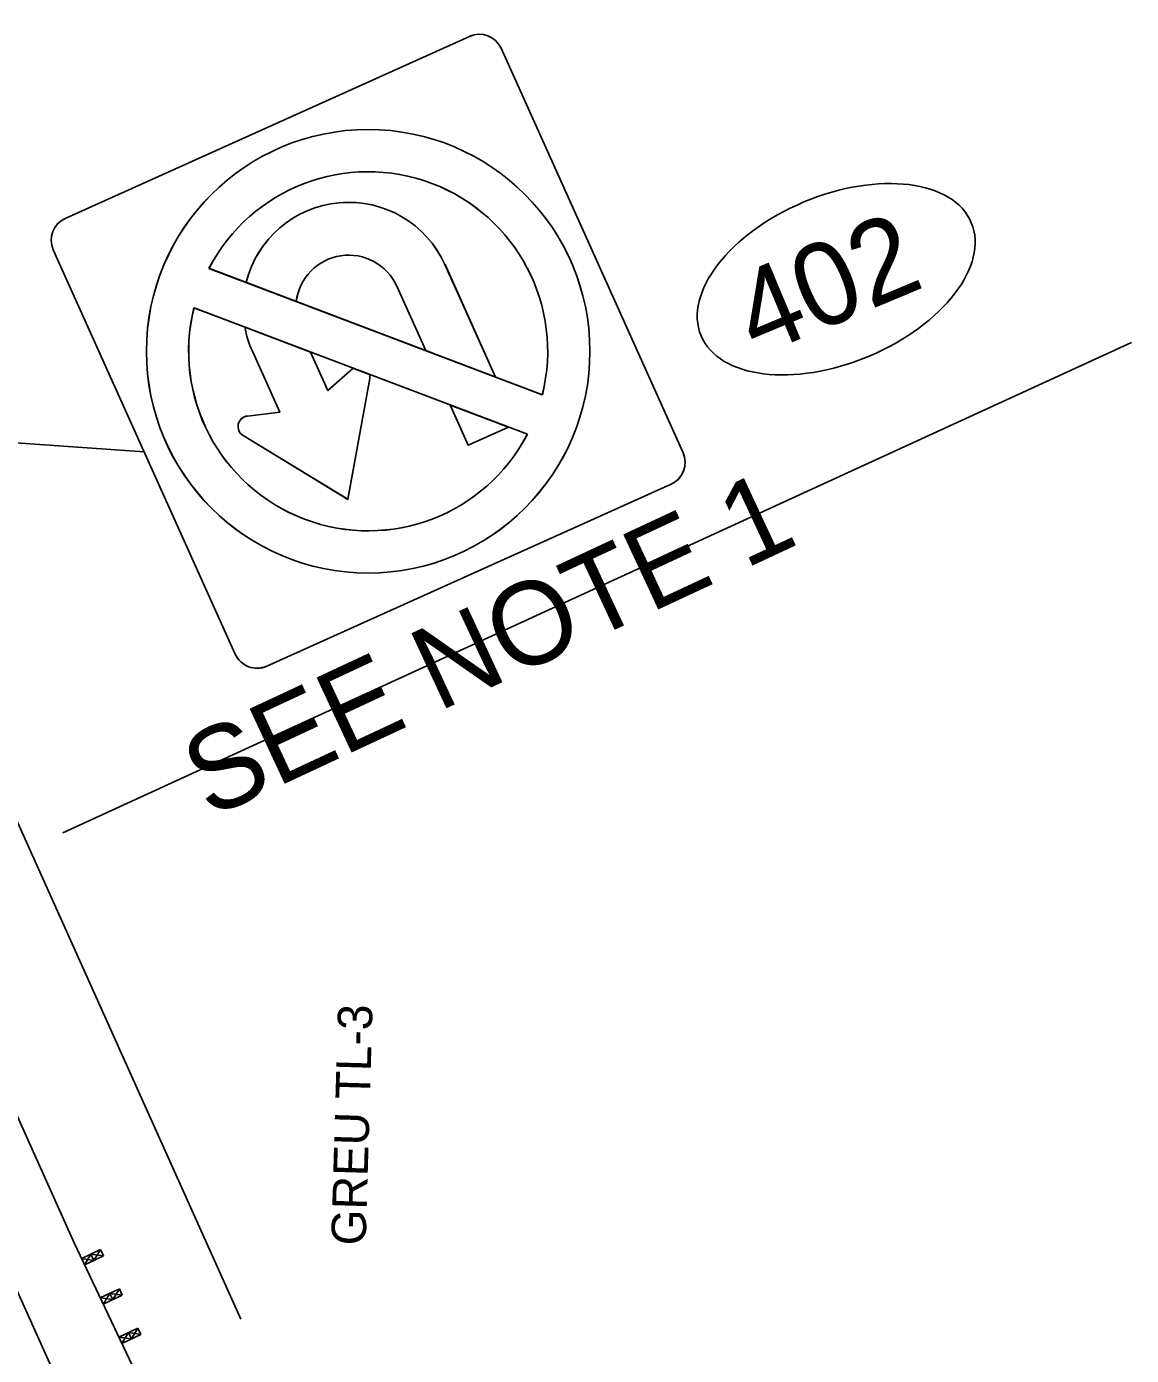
# Model space of a CAD drawing. Extents: x 2096670 to 2098561, y 684033 to 689893.
# Drawn here: x 2097858.5 to 2098018.6, y 685641.1 to 685833.7 of the extents above; entities that cross this region are included whole.
import ezdxf

# ---------------------------------------------------------------- set-up
doc = ezdxf.new("R2010")
doc.units = 0
for name, color, linetype in [('Exist Sign E No U Turn CELL', 7, 'Continuous'), ('Prop DSN Text', 7, 'Continuous'), ('Prop Guardrail', 7, 'Continuous'), ('Prop Guardrail Anchor Unit CELL', 7, 'Continuous'), ('Prop Sign E One Way_Right CELL', 7, 'Continuous'), ('Prop Sign E Signal Light Ahead CELL', 7, 'Continuous'), ('Scratch_Level_3', 7, 'Continuous'), ('Scratch_Level_4', 7, 'Continuous')]:
    doc.layers.add(name, color=color, linetype=linetype)

# ---------------------------------------------------------------- blocks, each defined once
blk = doc.blocks.new('Exist No U Turn')
at = {"layer": 'Exist Sign E No U Turn CELL'}
for p, q in [((56.27, 62.3), (-56.61, 62.3)), ((-62.66, 56.26), (-62.66, -56.62)), ((62.31, -56.62), (62.31, 56.26)), ((-28.46, 35.7), (35.71, -28.46)), ((-28.46, 35.7), (-28.46, 35.7)), ((-36.06, 28.1), (28.11, -36.06)), ((-36.06, 28.1), (-36.06, 28.1)), ((-21.29, 28.54), (-11.65, 18.9)), ((-21.29, 28.54), (-11.65, 18.9)), ((-21.29, 28.54), (-11.65, 18.9)), ((-11.65, 18.9), (-11.65, 18.9)), ((-11.65, 18.9), (-11.65, 18.9)), ((-11.65, 18.9), (-11.65, 18.9)), ((-2.25, -5.71), (-5.43, -2.52)), ((-2.67, -6.68), (-2.67, -6.68)), ((-2.67, -6.68), (-2.67, -6.68)), ((-56.61, -62.67), (56.27, -62.67))]:
    blk.add_line(p, q, dxfattribs=at)
for points in [[(-2.25, -5.71), (-5.45, -2.51), (-13.61, -5.1), (-13.61, 5.66), (-26.27, 18.32)], [(-5.72, -2.6), (-13.61, -5.1), (-13.61, 5.66), (-26.27, 18.32)], [(-2.25, -5.71), (-5.45, -2.51), (-13.61, -5.1), (-13.61, 5.66), (-26.27, 18.32)], [(-27.05, 11.91), (-27.05, -5.1), (-34.96, -2.59)], [(-27.05, 11.91), (-27.05, -5.1), (-34.96, -2.59)], [(-27.05, 11.91), (-27.05, -5.1), (-34.96, -2.59)], [(13.27, 11.91), (13.27, -6.02), (26.7, -19.46), (26.7, 11.91)], [(13.27, 11.91), (13.27, -6.02), (26.7, -19.46), (26.7, 11.91)], [(13.27, 11.91), (13.27, -6.02), (26.7, -19.46), (26.7, 11.91)], [(-38, -6.67), (-20.33, -32.43), (-2.67, -6.68)], [(-38, -6.67), (-20.33, -32.43), (-2.67, -6.68)], [(-38, -6.67), (-20.33, -32.43), (-2.67, -6.68)]]:
    blk.add_lwpolyline(points, dxfattribs=at)
blk.add_lwpolyline([(13.27, -21.22), (13.27, -32.43), (24.48, -32.43)], close=True, dxfattribs=at)
blk.add_lwpolyline([(13.27, -21.22), (13.27, -32.43), (24.48, -32.43)], close=True, dxfattribs=at)
blk.add_lwpolyline([(13.27, -21.22), (13.27, -32.43), (24.48, -32.43)], close=True, dxfattribs=at)
blk.add_circle((-0.17, -0.18), 56.44, dxfattribs=at)
for centre, radius, start, end in [((-56.61, 56.26), 6.05, 90, 180), ((56.27, 56.26), 6.05, 0, 90), ((-0.17, -0.18), 45.69, 321.7553, 128.2447), ((-0.17, 11.91), 26.88, 359.9928, 141.788), ((-0.17, 11.91), 26.88, 359.9928, 141.788), ((-0.17, 11.91), 26.88, 359.9928, 141.788), ((-0.17, -0.18), 45.69, 141.7553, 308.2447), ((-0.17, 11.91), 13.44, 0, 148.6739), ((-0.17, 11.91), 13.44, 0, 148.6739), ((-0.17, 11.91), 13.44, 0, 148.6739), ((-0.17, 11.91), 26.87, 166.2094, 180), ((-0.17, 11.91), 26.87, 166.2094, 180), ((-0.17, 11.91), 26.87, 166.2094, 180), ((-35.78, -5.15), 2.69, 72.3746, 214.4704), ((-35.78, -5.15), 2.69, 72.3746, 214.4704), ((-35.78, -5.15), 2.69, 72.3746, 214.4704), ((-4.9, -5.14), 2.67, 101.5336, 108.0305), ((-4.9, -5.14), 2.67, 101.5336, 107.1991), ((-4.9, -5.14), 2.67, 101.5336, 107.1991), ((-4.88, -5.15), 2.69, 325.4527, 348.1626), ((-4.88, -5.15), 2.69, 325.4527, 348.1626), ((-4.88, -5.15), 2.69, 325.4527, 348.1626), ((-56.61, -56.62), 6.05, 180, 270), ((56.27, -56.62), 6.05, 270, 0)]:
    blk.add_arc(centre, radius, start, end, dxfattribs=at)

msp = doc.modelspace()

# ---------------------------------------------------------------- linework, layer by layer
at = {"layer": 'Exist Sign E No U Turn CELL'}
for p, q in [((2097922.67, 685832.24), (2097864.06, 685805.86)), ((2097953.6, 685771.91), (2097927.22, 685830.52)), ((2097862.34, 685801.31), (2097888.71, 685742.71)), ((2097884.9, 685798.63), (2097933.21, 685780.31)), ((2097884.9, 685798.63), (2097884.9, 685798.63)), ((2097890.29, 685796.59), (2097897.55, 685793.83)), ((2097890.29, 685796.59), (2097897.55, 685793.83)), ((2097890.29, 685796.59), (2097897.55, 685793.83)), ((2097882.73, 685792.91), (2097931.04, 685774.59)), ((2097882.73, 685792.91), (2097882.73, 685792.91)), ((2097897.55, 685793.83), (2097897.55, 685793.83)), ((2097897.55, 685793.83), (2097897.55, 685793.83)), ((2097897.55, 685793.83), (2097897.55, 685793.83)), ((2097908.18, 685783.26), (2097905.78, 685784.17)), ((2097908.19, 685782.65), (2097908.19, 685782.65)), ((2097908.19, 685782.65), (2097908.19, 685782.65)), ((2097893.26, 685740.98), (2097951.87, 685767.36))]:
    msp.add_line(p, q, dxfattribs=at)
for points in [[(2097912.12, 685796.03), (2097916.31, 685786.72), (2097926.42, 685782.88), (2097919.1, 685799.17)], [(2097912.12, 685796.03), (2097916.31, 685786.72), (2097926.42, 685782.88), (2097919.1, 685799.17)], [(2097912.12, 685796.03), (2097916.31, 685786.72), (2097926.42, 685782.88), (2097919.1, 685799.17)], [(2097908.18, 685783.26), (2097905.77, 685784.17), (2097902.14, 685780.91), (2097899.63, 685786.5), (2097890.09, 685790.12)], [(2097905.65, 685784.06), (2097902.14, 685780.91), (2097899.63, 685786.5), (2097890.09, 685790.12)], [(2097908.18, 685783.26), (2097905.77, 685784.17), (2097902.14, 685780.91), (2097899.63, 685786.5), (2097890.09, 685790.12)], [(2097891.19, 685786.61), (2097895.16, 685777.77), (2097890.47, 685777.23)], [(2097891.19, 685786.61), (2097895.16, 685777.77), (2097890.47, 685777.23)], [(2097891.19, 685786.61), (2097895.16, 685777.77), (2097890.47, 685777.23)], [(2097889.85, 685774.4), (2097905.04, 685765.16), (2097908.19, 685782.65)], [(2097889.85, 685774.4), (2097905.04, 685765.16), (2097908.19, 685782.65)], [(2097889.85, 685774.4), (2097905.04, 685765.16), (2097908.19, 685782.65)]]:
    msp.add_lwpolyline(points, dxfattribs=at)
msp.add_lwpolyline([(2097919.86, 685778.83), (2097922.48, 685773.01), (2097928.3, 685775.63)], close=True, dxfattribs=at)
msp.add_lwpolyline([(2097919.86, 685778.83), (2097922.48, 685773.01), (2097928.3, 685775.63)], close=True, dxfattribs=at)
msp.add_lwpolyline([(2097919.86, 685778.83), (2097922.48, 685773.01), (2097928.3, 685775.63)], close=True, dxfattribs=at)
msp.add_circle((2097907.97, 685786.61), 32.13, dxfattribs=at)
for centre, radius, start, end in [((2097924.08, 685829.1), 3.44, 24.2309, 114.2309), ((2097907.97, 685786.61), 26.01, 345.9862, 152.4756), ((2097905.14, 685792.89), 15.3, 24.2237, 166.0189), ((2097905.14, 685792.89), 15.3, 24.2237, 166.0189), ((2097905.14, 685792.89), 15.3, 24.2237, 166.0189), ((2097865.48, 685802.73), 3.44, 114.2309, 204.2309), ((2097905.14, 685792.89), 7.65, 24.2309, 172.9048), ((2097905.14, 685792.89), 7.65, 24.2309, 172.9048), ((2097905.14, 685792.89), 7.65, 24.2309, 172.9048), ((2097907.97, 685786.61), 26.01, 165.9862, 332.4756), ((2097905.14, 685792.89), 15.3, 190.4403, 204.2309), ((2097905.14, 685792.89), 15.3, 190.4403, 204.2309), ((2097905.14, 685792.89), 15.3, 190.4403, 204.2309), ((2097906.67, 685782.93), 1.52, 125.7645, 132.2614), ((2097906.67, 685782.93), 1.52, 125.7645, 131.4301), ((2097906.67, 685782.93), 1.52, 125.7645, 131.4301), ((2097906.68, 685782.93), 1.53, 349.6837, 12.3936), ((2097906.68, 685782.93), 1.53, 349.6837, 12.3936), ((2097906.68, 685782.93), 1.53, 349.6837, 12.3936), ((2097890.64, 685775.71), 1.53, 96.6056, 238.7013), ((2097890.64, 685775.71), 1.53, 96.6056, 238.7013), ((2097890.64, 685775.71), 1.53, 96.6056, 238.7013), ((2097950.46, 685770.5), 3.44, 294.2309, 24.2309), ((2097891.85, 685744.12), 3.44, 204.2309, 294.2309)]:
    msp.add_arc(centre, radius, start, end, dxfattribs=at)
at = {"layer": 'Prop Guardrail'}
msp.add_line((2097865.36, 685657.45), (2097794.79, 685814.25), dxfattribs=at)
at = {"layer": 'Prop Guardrail Anchor Unit CELL'}
for p, q in [((2097865.36, 685657.45), (2097885.4, 685615.21)), ((2097866.45, 685655.15), (2097869.16, 685656.44)), ((2097868.23, 685654.89), (2097869.16, 685656.44)), ((2097869.16, 685656.44), (2097869.59, 685655.53)), ((2097866.45, 685655.15), (2097866.88, 685654.25)), ((2097868.23, 685654.89), (2097866.45, 685655.15)), ((2097867.8, 685655.79), (2097866.88, 685654.25)), ((2097866.88, 685654.25), (2097869.59, 685655.53)), ((2097866.88, 685654.25), (2097868.23, 685654.89)), ((2097867.8, 685655.79), (2097868.23, 685654.89)), ((2097869.59, 685655.53), (2097867.8, 685655.79)), ((2097869.15, 685649.46), (2097871.91, 685650.76)), ((2097870.96, 685649.21), (2097871.91, 685650.76)), ((2097871.91, 685650.76), (2097872.34, 685649.86)), ((2097869.15, 685649.46), (2097870.96, 685649.21)), ((2097870.53, 685650.11), (2097869.58, 685648.55)), ((2097869.58, 685648.55), (2097872.34, 685649.86)), ((2097870.53, 685650.11), (2097870.96, 685649.21)), ((2097872.34, 685649.86), (2097870.53, 685650.11)), ((2097871.85, 685643.76), (2097874.6, 685645.07)), ((2097873.23, 685644.42), (2097872.28, 685642.86)), ((2097873.23, 685644.42), (2097873.66, 685643.51)), ((2097875.03, 685644.17), (2097873.23, 685644.42)), ((2097873.66, 685643.51), (2097874.6, 685645.07)), ((2097874.6, 685645.07), (2097875.03, 685644.17)), ((2097871.85, 685643.76), (2097873.66, 685643.51)), ((2097872.28, 685642.86), (2097875.03, 685644.17))]:
    msp.add_line(p, q, dxfattribs=at)
at = {"layer": 'Prop Sign E One Way_Right CELL'}
msp.add_ellipse((2097975.79, 685797.05), major_axis=(-19.58, -8.19), ratio=0.571429, dxfattribs=at)
at = {"layer": 'Prop Sign E Signal Light Ahead CELL'}
for p, q in [((2097922.67, 685832.24), (2097864.06, 685805.86)), ((2097953.6, 685771.91), (2097927.22, 685830.52)), ((2097862.34, 685801.31), (2097888.71, 685742.71)), ((2097884.9, 685798.63), (2097933.21, 685780.31)), ((2097884.9, 685798.63), (2097884.9, 685798.63)), ((2097890.29, 685796.59), (2097897.55, 685793.83)), ((2097890.29, 685796.59), (2097897.55, 685793.83)), ((2097890.29, 685796.59), (2097897.55, 685793.83)), ((2097882.73, 685792.91), (2097931.04, 685774.59)), ((2097882.73, 685792.91), (2097882.73, 685792.91)), ((2097897.55, 685793.83), (2097897.55, 685793.83)), ((2097897.55, 685793.83), (2097897.55, 685793.83)), ((2097897.55, 685793.83), (2097897.55, 685793.83)), ((2097908.18, 685783.26), (2097905.78, 685784.17)), ((2097908.19, 685782.65), (2097908.19, 685782.65)), ((2097908.19, 685782.65), (2097908.19, 685782.65)), ((2097875.52, 685772.02), (2097773.38, 685779.3)), ((2097893.26, 685740.98), (2097951.87, 685767.36))]:
    msp.add_line(p, q, dxfattribs=at)
for points in [[(2097912.12, 685796.03), (2097916.31, 685786.72), (2097926.42, 685782.88), (2097919.1, 685799.17)], [(2097912.12, 685796.03), (2097916.31, 685786.72), (2097926.42, 685782.88), (2097919.1, 685799.17)], [(2097912.12, 685796.03), (2097916.31, 685786.72), (2097926.42, 685782.88), (2097919.1, 685799.17)], [(2097908.18, 685783.26), (2097905.77, 685784.17), (2097902.14, 685780.91), (2097899.63, 685786.5), (2097890.09, 685790.12)], [(2097905.65, 685784.06), (2097902.14, 685780.91), (2097899.63, 685786.5), (2097890.09, 685790.12)], [(2097908.18, 685783.26), (2097905.77, 685784.17), (2097902.14, 685780.91), (2097899.63, 685786.5), (2097890.09, 685790.12)], [(2097891.19, 685786.61), (2097895.16, 685777.77), (2097890.47, 685777.23)], [(2097891.19, 685786.61), (2097895.16, 685777.77), (2097890.47, 685777.23)], [(2097891.19, 685786.61), (2097895.16, 685777.77), (2097890.47, 685777.23)], [(2097889.85, 685774.4), (2097905.04, 685765.16), (2097908.19, 685782.65)], [(2097889.85, 685774.4), (2097905.04, 685765.16), (2097908.19, 685782.65)], [(2097889.85, 685774.4), (2097905.04, 685765.16), (2097908.19, 685782.65)]]:
    msp.add_lwpolyline(points, dxfattribs=at)
msp.add_lwpolyline([(2097919.86, 685778.83), (2097922.48, 685773.01), (2097928.3, 685775.63)], close=True, dxfattribs=at)
msp.add_lwpolyline([(2097919.86, 685778.83), (2097922.48, 685773.01), (2097928.3, 685775.63)], close=True, dxfattribs=at)
msp.add_lwpolyline([(2097919.86, 685778.83), (2097922.48, 685773.01), (2097928.3, 685775.63)], close=True, dxfattribs=at)
msp.add_circle((2097907.97, 685786.61), 32.13, dxfattribs=at)
for centre, radius, start, end in [((2097924.08, 685829.1), 3.44, 24.2309, 114.2309), ((2097907.97, 685786.61), 26.01, 345.9862, 152.4756), ((2097905.14, 685792.89), 15.3, 24.2237, 166.0189), ((2097905.14, 685792.89), 15.3, 24.2237, 166.0189), ((2097905.14, 685792.89), 15.3, 24.2237, 166.0189), ((2097865.48, 685802.73), 3.44, 114.2309, 204.2309), ((2097905.14, 685792.89), 7.65, 24.2309, 172.9048), ((2097905.14, 685792.89), 7.65, 24.2309, 172.9048), ((2097905.14, 685792.89), 7.65, 24.2309, 172.9048), ((2097907.97, 685786.61), 26.01, 165.9862, 332.4756), ((2097905.14, 685792.89), 15.3, 190.4403, 204.2309), ((2097905.14, 685792.89), 15.3, 190.4403, 204.2309), ((2097905.14, 685792.89), 15.3, 190.4403, 204.2309), ((2097906.67, 685782.93), 1.52, 125.7645, 132.2614), ((2097906.67, 685782.93), 1.52, 125.7645, 131.4301), ((2097906.67, 685782.93), 1.52, 125.7645, 131.4301), ((2097906.68, 685782.93), 1.53, 349.6837, 12.3936), ((2097906.68, 685782.93), 1.53, 349.6837, 12.3936), ((2097906.68, 685782.93), 1.53, 349.6837, 12.3936), ((2097890.64, 685775.71), 1.53, 96.6056, 238.7013), ((2097890.64, 685775.71), 1.53, 96.6056, 238.7013), ((2097890.64, 685775.71), 1.53, 96.6056, 238.7013), ((2097950.46, 685770.5), 3.44, 294.2309, 24.2309), ((2097891.85, 685744.12), 3.44, 204.2309, 294.2309)]:
    msp.add_arc(centre, radius, start, end, dxfattribs=at)
at = {"layer": 'Scratch_Level_3'}
msp.add_line((2097863.72, 685716.84), (2098018.57, 685787.89), dxfattribs=at)
at = {"layer": 'Scratch_Level_4'}
msp.add_line((2097889.53, 685646.39), (2097810.74, 685821.44), dxfattribs=at)
msp.add_lwpolyline([(2097918.23, 685516.37), (2097897.05, 685562.45), (2097876.09, 685608.28), (2097855.55, 685653.89), (2097835.25, 685699.31)], dxfattribs=at)

# ---------------------------------------------------------------- block references
at = {"layer": 'Prop Sign E One Way_Right CELL', "xscale": 0.5693769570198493, "yscale": 0.5693769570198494, "rotation": 24.230915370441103}
msp.add_blockref('Exist No U Turn', (2097908.01, 685786.74), dxfattribs=at)
at = {"layer": 'Prop Sign E Signal Light Ahead CELL', "xscale": 0.5693769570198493, "yscale": 0.5693769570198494, "rotation": 24.230915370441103}
msp.add_blockref('Exist No U Turn', (2097908.01, 685786.74), dxfattribs=at)

# ---------------------------------------------------------------- texts
at = {"layer": 'Prop DSN Text'}
msp.add_text('SEE NOTE 1', height=12, rotation=25.0045, dxfattribs=at).set_placement((2097884.97, 685718.86))
at = {"layer": 'Prop Guardrail Anchor Unit CELL'}
msp.add_text('GREU TL-3', height=5, rotation=88.3348, dxfattribs=at).set_placement((2097907.6, 685657))
at = {"layer": 'Prop Sign E One Way_Right CELL'}
msp.add_text('402', height=11.98, rotation=22.6926, dxfattribs=at).set_placement((2097964.27, 685785.75))

doc.saveas('drawing.dxf')
